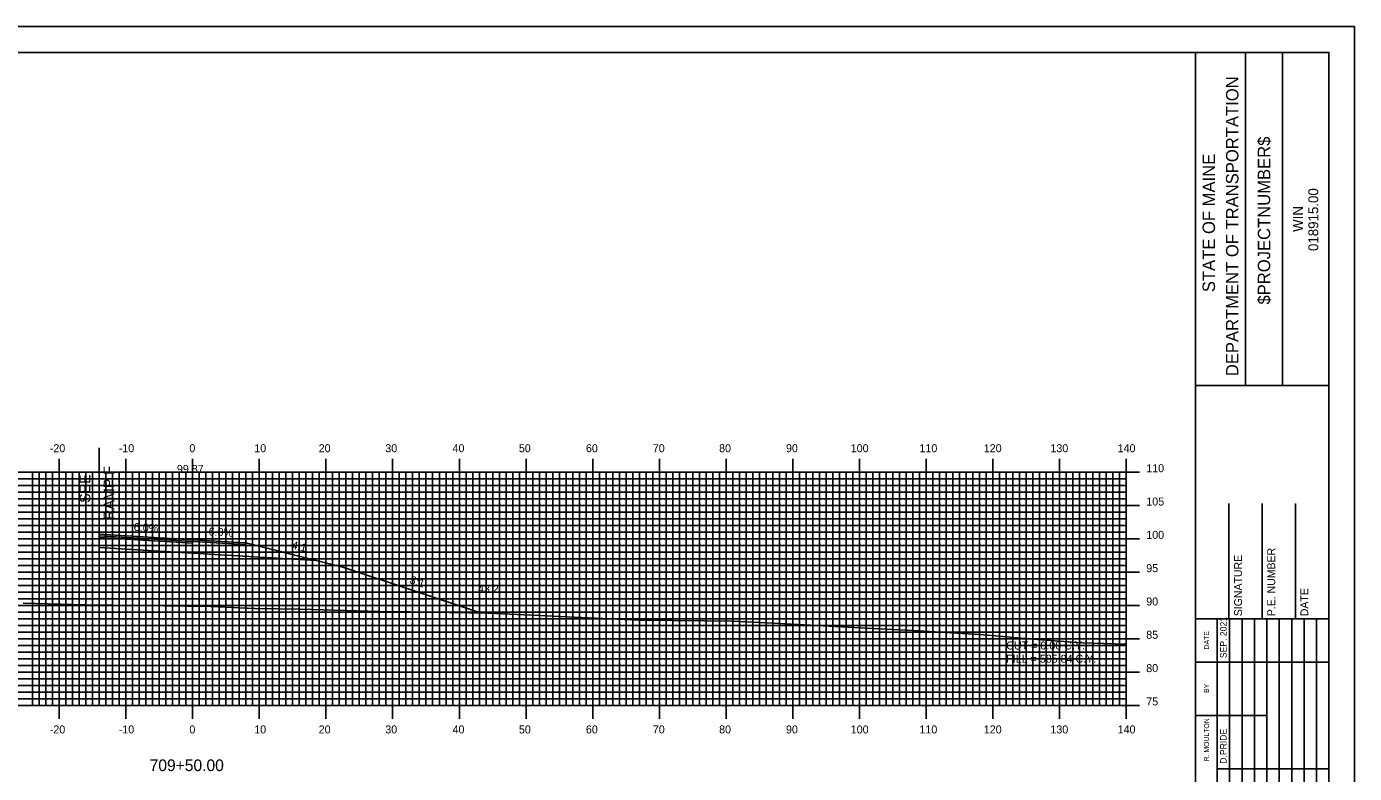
# Model space of a CAD drawing. Extents: x 854510 to 854853, y 364366 to 364586.
# Drawn here: x 854650.8 to 854850, y 364473.6 to 364585.7 of the extents above; entities that cross this region are included whole.
import ezdxf

# ---------------------------------------------------------------- set-up
doc = ezdxf.new("R2010")
doc.units = 0
for name, color, linetype in [('ANNOTATION', 7, 'Continuous'), ('BORDER', 7, 'Continuous'), ('D_Roadway_Centerline', 7, 'Continuous'), ('D_Roadway_Centerline_Text', 7, 'Continuous'), ('D_Roadway_Edge_Shoulder', 7, 'Continuous'), ('D_Roadway_Edge_TW', 7, 'Continuous'), ('D_Roadway_Pavement', 7, 'Continuous'), ('D_Roadway_SlopeLines', 7, 'Continuous'), ('D_Roadway_SubGrade', 7, 'Continuous'), ('D_Text_Standard', 7, 'Continuous'), ('H_V ANNOTATION', 7, 'Continuous'), ('MAJOR', 7, 'Continuous'), ('MINOR', 7, 'Continuous'), ('PLOT BOUNDARY', 7, 'Continuous'), ('S_Roadway_Centerline', 7, 'Continuous')]:
    doc.layers.add(name, color=color, linetype=linetype)

msp = doc.modelspace()

# ---------------------------------------------------------------- linework, layer by layer
at = {"layer": 'BORDER'}
for p, q in [((854826.14, 364371.79), (854826.14, 364581.79)), ((854833.6, 364531.78), (854833.6, 364581.78)), ((854839.19, 364531.78), (854839.19, 364581.78)), ((854826.15, 364531.78), (854846.14, 364531.78)), ((854831.14, 364496.79), (854831.14, 364514.09)), ((854836.14, 364496.79), (854836.14, 364514.09)), ((854841.14, 364496.79), (854841.14, 364514.09)), ((854826.14, 364496.79), (854846.14, 364496.79))]:
    msp.add_line(p, q, dxfattribs=at)
msp.add_lwpolyline([(854526.14, 364371.79), (854846.14, 364371.79), (854846.14, 364581.79), (854526.14, 364581.79)], close=True, dxfattribs=at)
for points in [[(854829.37, 364490.29), (854829.37, 364496.79)], [(854831.24, 364461.8), (854831.24, 364496.79)], [(854833.1, 364496.79), (854833.1, 364461.8)], [(854834.97, 364461.8), (854834.97, 364496.79)], [(854836.83, 364461.8), (854836.83, 364496.79)], [(854838.69, 364461.8), (854838.69, 364496.79)], [(854840.56, 364461.8), (854840.56, 364496.79)], [(854842.42, 364461.8), (854842.42, 364496.79)], [(854844.28, 364461.8), (854844.28, 364496.79)], [(854829.38, 364461.8), (854829.38, 364495.38)], [(854826.14, 364490.29), (854846.14, 364490.29)], [(854826.14, 364482.29), (854829.38, 364482.29)], [(854829.37, 364482.29), (854836.83, 364482.29)], [(854829.37, 364474.29), (854846.14, 364474.29)]]:
    msp.add_lwpolyline(points, dxfattribs=at)
at = {"layer": 'D_Roadway_Centerline'}
msp.add_lwpolyline([(854661.74, 364509.5), (854675.74, 364508.66), (854683.74, 364508.18), (854694.27, 364505.55), (854698.27, 364504.55), (854718.91, 364497.67)], dxfattribs=at)
at = {"layer": 'D_Roadway_Edge_Shoulder'}
msp.add_lwpolyline([(854675.74, 364508.66), (854683.74, 364508.18), (854683.74, 364507.93), (854675.74, 364508.41)], close=True, dxfattribs=at)
at = {"layer": 'D_Roadway_Edge_TW'}
msp.add_lwpolyline([(854661.74, 364509.5), (854675.74, 364508.66), (854675.74, 364508.41), (854661.74, 364509.25)], close=True, dxfattribs=at)
at = {"layer": 'D_Roadway_Pavement'}
msp.add_lwpolyline([(854661.74, 364509.25), (854675.74, 364508.41), (854675.74, 364508.16), (854661.74, 364509)], close=True, dxfattribs=at)
msp.add_lwpolyline([(854675.74, 364508.41), (854675.74, 364508.16)], dxfattribs=at)
at = {"layer": 'D_Roadway_SlopeLines'}
msp.add_lwpolyline([(854683.74, 364508.18), (854698.27, 364504.55), (854718.91, 364497.67)], dxfattribs=at)
at = {"layer": 'D_Roadway_SubGrade'}
msp.add_line((854661.74, 364522.46), (854661.74, 364507.5), dxfattribs=at)
for points in [[(854661.74, 364509), (854675.74, 364508.16), (854675.74, 364506.66), (854661.74, 364507.5)], [(854675.74, 364508.16), (854675.74, 364508.41), (854683.74, 364507.93), (854683.74, 364508.18), (854694.27, 364505.55), (854675.74, 364506.66)]]:
    msp.add_lwpolyline(points, close=True, dxfattribs=at)
at = {"layer": 'MAJOR'}
for p, q in [((854655.74, 364520.79), (854655.74, 364518.79)), ((854665.74, 364520.79), (854665.74, 364518.79)), ((854675.74, 364520.79), (854675.74, 364518.79)), ((854685.74, 364520.79), (854685.74, 364518.79)), ((854695.74, 364520.79), (854695.74, 364518.79)), ((854705.74, 364520.79), (854705.74, 364518.79)), ((854715.74, 364520.79), (854715.74, 364518.79)), ((854725.74, 364520.79), (854725.74, 364518.79)), ((854735.74, 364520.79), (854735.74, 364518.79)), ((854745.74, 364520.79), (854745.74, 364518.79)), ((854755.74, 364520.79), (854755.74, 364518.79)), ((854765.74, 364520.79), (854765.74, 364518.79)), ((854775.74, 364520.79), (854775.74, 364518.79)), ((854785.74, 364520.79), (854785.74, 364518.79)), ((854795.74, 364520.79), (854795.74, 364518.79)), ((854805.74, 364520.79), (854805.74, 364518.79)), ((854815.74, 364520.79), (854815.74, 364518.79)), ((854535.74, 364518.79), (854815.74, 364518.79)), ((854535.74, 364518.79), (854815.74, 364518.79)), ((854655.74, 364483.79), (854655.74, 364518.79)), ((854665.74, 364483.79), (854665.74, 364518.79)), ((854675.74, 364483.79), (854675.74, 364518.79)), ((854685.74, 364483.79), (854685.74, 364518.79)), ((854695.74, 364483.79), (854695.74, 364518.79)), ((854705.74, 364483.79), (854705.74, 364518.79)), ((854715.74, 364483.79), (854715.74, 364518.79)), ((854725.74, 364483.79), (854725.74, 364518.79)), ((854735.74, 364483.79), (854735.74, 364518.79)), ((854745.74, 364483.79), (854745.74, 364518.79)), ((854755.74, 364483.79), (854755.74, 364518.79)), ((854765.74, 364483.79), (854765.74, 364518.79)), ((854775.74, 364483.79), (854775.74, 364518.79)), ((854785.74, 364483.79), (854785.74, 364518.79)), ((854795.74, 364483.79), (854795.74, 364518.79)), ((854805.74, 364483.79), (854805.74, 364518.79)), ((854817.75, 364518.79), (854813.74, 364518.79)), ((854815.74, 364483.79), (854815.74, 364518.79)), ((854815.74, 364483.79), (854815.74, 364518.79)), ((854535.74, 364513.79), (854815.74, 364513.79)), ((854817.75, 364513.79), (854813.74, 364513.79)), ((854535.74, 364508.79), (854815.74, 364508.79)), ((854817.75, 364508.79), (854813.74, 364508.79)), ((854535.74, 364503.79), (854815.74, 364503.79)), ((854817.75, 364503.79), (854813.74, 364503.79)), ((854535.74, 364498.79), (854815.74, 364498.79)), ((854817.75, 364498.79), (854813.74, 364498.79)), ((854535.74, 364493.79), (854815.74, 364493.79)), ((854817.75, 364493.79), (854813.74, 364493.79)), ((854535.74, 364488.79), (854815.74, 364488.79)), ((854817.75, 364488.79), (854813.74, 364488.79)), ((854535.74, 364483.79), (854815.74, 364483.79)), ((854535.74, 364483.79), (854815.74, 364483.79)), ((854655.74, 364481.78), (854655.74, 364483.79)), ((854665.74, 364481.78), (854665.74, 364483.79)), ((854675.74, 364481.78), (854675.74, 364483.79)), ((854685.74, 364481.78), (854685.74, 364483.79)), ((854695.74, 364481.78), (854695.74, 364483.79)), ((854705.74, 364481.78), (854705.74, 364483.79)), ((854715.74, 364481.78), (854715.74, 364483.79)), ((854725.74, 364481.78), (854725.74, 364483.79)), ((854735.74, 364481.78), (854735.74, 364483.79)), ((854745.74, 364481.78), (854745.74, 364483.79)), ((854755.74, 364481.78), (854755.74, 364483.79)), ((854765.74, 364481.78), (854765.74, 364483.79)), ((854775.74, 364481.78), (854775.74, 364483.79)), ((854785.74, 364481.78), (854785.74, 364483.79)), ((854795.74, 364481.78), (854795.74, 364483.79)), ((854805.74, 364481.78), (854805.74, 364483.79)), ((854817.75, 364483.79), (854813.74, 364483.79)), ((854815.74, 364481.78), (854815.74, 364483.79))]:
    msp.add_line(p, q, dxfattribs=at)
at = {"layer": 'MINOR'}
for p, q in [((854535.74, 364517.79), (854815.74, 364517.79)), ((854651.74, 364483.79), (854651.74, 364518.79)), ((854652.74, 364483.79), (854652.74, 364518.79)), ((854653.74, 364483.79), (854653.74, 364518.79)), ((854654.74, 364483.79), (854654.74, 364518.79)), ((854656.74, 364483.79), (854656.74, 364518.79)), ((854657.74, 364483.79), (854657.74, 364518.79)), ((854658.74, 364483.79), (854658.74, 364518.79)), ((854659.74, 364483.79), (854659.74, 364518.79)), ((854660.74, 364483.79), (854660.74, 364518.79)), ((854661.74, 364483.79), (854661.74, 364518.79)), ((854662.74, 364483.79), (854662.74, 364518.79)), ((854663.74, 364483.79), (854663.74, 364518.79)), ((854664.74, 364483.79), (854664.74, 364518.79)), ((854666.74, 364483.79), (854666.74, 364518.79)), ((854667.74, 364483.79), (854667.74, 364518.79)), ((854668.74, 364483.79), (854668.74, 364518.79)), ((854669.74, 364483.79), (854669.74, 364518.79)), ((854670.74, 364483.79), (854670.74, 364518.79)), ((854671.74, 364483.79), (854671.74, 364518.79)), ((854672.74, 364483.79), (854672.74, 364518.79)), ((854673.74, 364483.79), (854673.74, 364518.79)), ((854674.74, 364483.79), (854674.74, 364518.79)), ((854676.74, 364483.79), (854676.74, 364518.79)), ((854677.74, 364483.79), (854677.74, 364518.79)), ((854678.74, 364483.79), (854678.74, 364518.79)), ((854679.74, 364483.79), (854679.74, 364518.79)), ((854680.74, 364483.79), (854680.74, 364518.79)), ((854681.74, 364483.79), (854681.74, 364518.79)), ((854682.74, 364483.79), (854682.74, 364518.79)), ((854683.74, 364483.79), (854683.74, 364518.79)), ((854684.74, 364483.79), (854684.74, 364518.79)), ((854686.74, 364483.79), (854686.74, 364518.79)), ((854687.74, 364483.79), (854687.74, 364518.79)), ((854688.74, 364483.79), (854688.74, 364518.79)), ((854689.74, 364483.79), (854689.74, 364518.79)), ((854690.74, 364483.79), (854690.74, 364518.79)), ((854691.74, 364483.79), (854691.74, 364518.79)), ((854692.74, 364483.79), (854692.74, 364518.79)), ((854693.74, 364483.79), (854693.74, 364518.79)), ((854694.74, 364483.79), (854694.74, 364518.79)), ((854696.74, 364483.79), (854696.74, 364518.79)), ((854697.74, 364483.79), (854697.74, 364518.79)), ((854698.74, 364483.79), (854698.74, 364518.79)), ((854699.74, 364483.79), (854699.74, 364518.79)), ((854700.74, 364483.79), (854700.74, 364518.79)), ((854701.74, 364483.79), (854701.74, 364518.79)), ((854702.74, 364483.79), (854702.74, 364518.79)), ((854703.74, 364483.79), (854703.74, 364518.79)), ((854704.74, 364483.79), (854704.74, 364518.79)), ((854706.74, 364483.79), (854706.74, 364518.79)), ((854707.74, 364483.79), (854707.74, 364518.79)), ((854708.74, 364483.79), (854708.74, 364518.79)), ((854709.74, 364483.79), (854709.74, 364518.79)), ((854710.74, 364483.79), (854710.74, 364518.79)), ((854711.74, 364483.79), (854711.74, 364518.79)), ((854712.74, 364483.79), (854712.74, 364518.79)), ((854713.74, 364483.79), (854713.74, 364518.79)), ((854714.74, 364483.79), (854714.74, 364518.79)), ((854716.74, 364483.79), (854716.74, 364518.79)), ((854717.74, 364483.79), (854717.74, 364518.79)), ((854718.74, 364483.79), (854718.74, 364518.79)), ((854719.74, 364483.79), (854719.74, 364518.79)), ((854720.74, 364483.79), (854720.74, 364518.79)), ((854721.74, 364483.79), (854721.74, 364518.79)), ((854722.74, 364483.79), (854722.74, 364518.79)), ((854723.74, 364483.79), (854723.74, 364518.79)), ((854724.74, 364483.79), (854724.74, 364518.79)), ((854726.74, 364483.79), (854726.74, 364518.79)), ((854727.74, 364483.79), (854727.74, 364518.79)), ((854728.74, 364483.79), (854728.74, 364518.79)), ((854729.74, 364483.79), (854729.74, 364518.79)), ((854730.74, 364483.79), (854730.74, 364518.79)), ((854731.74, 364483.79), (854731.74, 364518.79)), ((854732.74, 364483.79), (854732.74, 364518.79)), ((854733.74, 364483.79), (854733.74, 364518.79)), ((854734.74, 364483.79), (854734.74, 364518.79)), ((854736.74, 364483.79), (854736.74, 364518.79)), ((854737.74, 364483.79), (854737.74, 364518.79)), ((854738.74, 364483.79), (854738.74, 364518.79)), ((854739.74, 364483.79), (854739.74, 364518.79)), ((854740.74, 364483.79), (854740.74, 364518.79)), ((854741.74, 364483.79), (854741.74, 364518.79)), ((854742.74, 364483.79), (854742.74, 364518.79)), ((854743.74, 364483.79), (854743.74, 364518.79)), ((854744.74, 364483.79), (854744.74, 364518.79)), ((854746.74, 364483.79), (854746.74, 364518.79)), ((854747.74, 364483.79), (854747.74, 364518.79)), ((854748.74, 364483.79), (854748.74, 364518.79)), ((854749.74, 364483.79), (854749.74, 364518.79)), ((854750.74, 364483.79), (854750.74, 364518.79)), ((854751.74, 364483.79), (854751.74, 364518.79)), ((854752.74, 364483.79), (854752.74, 364518.79)), ((854753.74, 364483.79), (854753.74, 364518.79)), ((854754.74, 364483.79), (854754.74, 364518.79)), ((854756.74, 364483.79), (854756.74, 364518.79)), ((854757.74, 364483.79), (854757.74, 364518.79)), ((854758.74, 364483.79), (854758.74, 364518.79)), ((854759.74, 364483.79), (854759.74, 364518.79)), ((854760.74, 364483.79), (854760.74, 364518.79)), ((854761.74, 364483.79), (854761.74, 364518.79)), ((854762.74, 364483.79), (854762.74, 364518.79)), ((854763.74, 364483.79), (854763.74, 364518.79)), ((854764.74, 364483.79), (854764.74, 364518.79)), ((854766.74, 364483.79), (854766.74, 364518.79)), ((854767.74, 364483.79), (854767.74, 364518.79)), ((854768.74, 364483.79), (854768.74, 364518.79)), ((854769.74, 364483.79), (854769.74, 364518.79)), ((854770.74, 364483.79), (854770.74, 364518.79)), ((854771.74, 364483.79), (854771.74, 364518.79)), ((854772.74, 364483.79), (854772.74, 364518.79)), ((854773.74, 364483.79), (854773.74, 364518.79)), ((854774.74, 364483.79), (854774.74, 364518.79)), ((854776.74, 364483.79), (854776.74, 364518.79)), ((854777.74, 364483.79), (854777.74, 364518.79)), ((854778.74, 364483.79), (854778.74, 364518.79)), ((854779.74, 364483.79), (854779.74, 364518.79)), ((854780.74, 364483.79), (854780.74, 364518.79)), ((854781.74, 364483.79), (854781.74, 364518.79)), ((854782.74, 364483.79), (854782.74, 364518.79)), ((854783.74, 364483.79), (854783.74, 364518.79)), ((854784.74, 364483.79), (854784.74, 364518.79)), ((854786.74, 364483.79), (854786.74, 364518.79)), ((854787.74, 364483.79), (854787.74, 364518.79)), ((854788.74, 364483.79), (854788.74, 364518.79)), ((854789.74, 364483.79), (854789.74, 364518.79)), ((854790.74, 364483.79), (854790.74, 364518.79)), ((854791.74, 364483.79), (854791.74, 364518.79)), ((854792.74, 364483.79), (854792.74, 364518.79)), ((854793.74, 364483.79), (854793.74, 364518.79)), ((854794.74, 364483.79), (854794.74, 364518.79)), ((854796.74, 364483.79), (854796.74, 364518.79)), ((854797.74, 364483.79), (854797.74, 364518.79)), ((854798.74, 364483.79), (854798.74, 364518.79)), ((854799.74, 364483.79), (854799.74, 364518.79)), ((854800.74, 364483.79), (854800.74, 364518.79)), ((854801.74, 364483.79), (854801.74, 364518.79)), ((854802.74, 364483.79), (854802.74, 364518.79)), ((854803.74, 364483.79), (854803.74, 364518.79)), ((854804.74, 364483.79), (854804.74, 364518.79)), ((854806.74, 364483.79), (854806.74, 364518.79)), ((854807.74, 364483.79), (854807.74, 364518.79)), ((854808.74, 364483.79), (854808.74, 364518.79)), ((854809.74, 364483.79), (854809.74, 364518.79)), ((854810.74, 364483.79), (854810.74, 364518.79)), ((854811.74, 364483.79), (854811.74, 364518.79)), ((854812.74, 364483.79), (854812.74, 364518.79)), ((854813.74, 364483.79), (854813.74, 364518.79)), ((854815.74, 364517.79), (854813.74, 364517.79)), ((854814.74, 364483.79), (854814.74, 364518.79)), ((854535.74, 364516.79), (854815.74, 364516.79)), ((854535.74, 364515.79), (854815.74, 364515.79)), ((854815.74, 364516.79), (854813.74, 364516.79)), ((854815.74, 364515.79), (854813.74, 364515.79)), ((854535.74, 364514.79), (854815.74, 364514.79)), ((854815.74, 364514.79), (854813.74, 364514.79)), ((854535.74, 364512.79), (854815.74, 364512.79)), ((854535.74, 364511.79), (854815.74, 364511.79)), ((854815.74, 364512.79), (854813.74, 364512.79)), ((854815.74, 364511.79), (854813.74, 364511.79)), ((854535.74, 364510.79), (854815.74, 364510.79)), ((854535.74, 364509.79), (854815.74, 364509.79)), ((854815.74, 364510.79), (854813.74, 364510.79)), ((854815.74, 364509.79), (854813.74, 364509.79)), ((854535.74, 364507.79), (854815.74, 364507.79)), ((854815.74, 364507.79), (854813.74, 364507.79)), ((854535.74, 364506.79), (854815.74, 364506.79)), ((854535.74, 364505.79), (854815.74, 364505.79)), ((854815.74, 364506.79), (854813.74, 364506.79)), ((854815.74, 364505.79), (854813.74, 364505.79)), ((854535.74, 364504.79), (854815.74, 364504.79)), ((854815.74, 364504.79), (854813.74, 364504.79)), ((854535.74, 364502.79), (854815.74, 364502.79)), ((854535.74, 364501.79), (854815.74, 364501.79)), ((854815.74, 364502.79), (854813.74, 364502.79)), ((854815.74, 364501.79), (854813.74, 364501.79)), ((854535.74, 364500.79), (854815.74, 364500.79)), ((854535.74, 364499.79), (854815.74, 364499.79)), ((854815.74, 364500.79), (854813.74, 364500.79)), ((854815.74, 364499.79), (854813.74, 364499.79)), ((854535.74, 364497.79), (854815.74, 364497.79)), ((854815.74, 364497.79), (854813.74, 364497.79)), ((854535.74, 364496.79), (854815.74, 364496.79)), ((854535.74, 364495.79), (854815.74, 364495.79)), ((854815.74, 364496.79), (854813.74, 364496.79)), ((854815.74, 364495.79), (854813.74, 364495.79)), ((854535.74, 364494.79), (854815.74, 364494.79)), ((854815.74, 364494.79), (854813.74, 364494.79)), ((854535.74, 364492.79), (854815.74, 364492.79)), ((854815.74, 364492.79), (854813.74, 364492.79)), ((854535.74, 364491.79), (854815.74, 364491.79)), ((854535.74, 364490.79), (854815.74, 364490.79)), ((854815.74, 364491.79), (854813.74, 364491.79)), ((854815.74, 364490.79), (854813.74, 364490.79)), ((854535.74, 364489.79), (854815.74, 364489.79)), ((854815.74, 364489.79), (854813.74, 364489.79)), ((854535.74, 364487.79), (854815.74, 364487.79)), ((854535.74, 364486.79), (854815.74, 364486.79)), ((854815.74, 364487.79), (854813.74, 364487.79)), ((854815.74, 364486.79), (854813.74, 364486.79)), ((854535.74, 364485.79), (854815.74, 364485.79)), ((854535.74, 364484.79), (854815.74, 364484.79)), ((854815.74, 364485.79), (854813.74, 364485.79)), ((854815.74, 364484.79), (854813.74, 364484.79))]:
    msp.add_line(p, q, dxfattribs=at)
at = {"layer": 'PLOT BOUNDARY'}
msp.add_lwpolyline([(854509.96, 364365.67), (854849.96, 364365.67), (854849.96, 364585.67), (854509.96, 364585.67)], close=True, dxfattribs=at)
at = {"layer": 'S_Roadway_Centerline'}
msp.add_lwpolyline([(854650.32, 364499.13), (854659.66, 364498.9), (854667.94, 364498.79), (854678.5, 364498.62), (854685.03, 364498.32), (854691.86, 364498.26), (854703.71, 364497.88), (854708.37, 364497.82), (854720.06, 364497.65), (854729.8, 364497.19), (854738.31, 364496.77), (854742.68, 364496.59), (854752.44, 364496.5), (854756.9, 364496.43), (854768.38, 364495.84), (854773.11, 364495.59), (854784.64, 364494.98), (854791.12, 364494.58), (854793.86, 364494.44), (854801.1, 364493.81), (854809.05, 364493.16), (854815.74, 364492.98)], dxfattribs=at)

# ---------------------------------------------------------------- texts
at = {"layer": 'ANNOTATION'}
for s, height, rotation, p in [('SEE', 1.6, 90, (854660.4, 364514.18)), ('RAMP F', 1.6, 90, (854664, 364511.64)), ('6.0%', 1.2, 356.5664, (854666.9, 364509.99)), ('-6.0%', 1.2, 356.5664, (854677.58, 364509.35)), ('4:1', 1.2, 345.9638, (854690.51, 364507.35)), ('3:1', 1.2, 341.5652, (854708.19, 364502.15))]:
    msp.add_text(s, height=height, rotation=rotation, dxfattribs=at).set_placement(p)
at = {"layer": 'BORDER'}
for s, height, p in [('DEPARTMENT OF TRANSPORTATION', 1.8635, (854832.56, 364533.2)), ('$PROJECTNUMBER$', 1.8635, (854837.33, 364543.95)), ('STATE OF MAINE', 1.8635, (854829.05, 364545.81)), ('018915.00', 1.491, (854844.53, 364551.98)), ('WIN', 1.491, (854842.22, 364554.85)), ('SIGNATURE', 1.181, (854833.1, 364497.18)), ('P.E. NUMBER', 1.1811, (854838.07, 364497.18)), ('DATE', 1.181, (854843.03, 364497.18)), ('SEP. 2021', 0.969, (854830.79, 364490.88)), ('DATE', 0.743, (854828.15, 364492.2)), ('BY', 0.743, (854828.15, 364485.66)), ('R. MOULTON', 0.745, (854828.15, 364475.4)), ('D.PRIDE', 0.969, (854830.79, 364475.04))]:
    msp.add_text(s, height=height, rotation=90, dxfattribs=at).set_placement(p)
at = {"layer": 'D_Roadway_Centerline_Text'}
msp.add_text('99.87', height=1.2, dxfattribs=at).set_placement((854673.39, 364518.68))
at = {"layer": 'D_Text_Standard'}
for s, p in [("43.2'", (854718.53, 364500.69)), ('CUT = 0.00 C.Y.', (854797.74, 364492.19)), ('FILL = 585.84 C.Y.', (854797.74, 364490.2))]:
    msp.add_text(s, height=1.2, dxfattribs=at).set_placement(p)
at = {"layer": 'H_V ANNOTATION'}
for s, height, p in [('-20', 1.2, (854654.33, 364521.79)), ('-10', 1.2, (854664.67, 364521.79)), ('0', 1.2, (854675.26, 364521.79)), ('10', 1.2, (854684.99, 364521.79)), ('20', 1.2, (854694.65, 364521.79)), ('30', 1.2, (854704.64, 364521.79)), ('40', 1.2, (854714.72, 364521.79)), ('50', 1.2, (854724.67, 364521.79)), ('60', 1.2, (854734.72, 364521.79)), ('70', 1.2, (854744.75, 364521.79)), ('80', 1.2, (854754.69, 364521.79)), ('90', 1.2, (854764.72, 364521.79)), ('100', 1.2, (854774.43, 364521.79)), ('110', 1.2, (854784.73, 364521.79)), ('120', 1.2, (854794.38, 364521.79)), ('130', 1.2, (854804.37, 364521.79)), ('140', 1.2, (854814.45, 364521.79)), ('110', 1.2, (854818.74, 364518.79)), ('105', 1.2, (854818.74, 364513.79)), ('100', 1.2, (854818.74, 364508.79)), ('95', 1.2, (854818.74, 364503.79)), ('90', 1.2, (854818.74, 364498.79)), ('85', 1.2, (854818.74, 364493.79)), ('80', 1.2, (854818.74, 364488.79)), ('75', 1.2, (854818.74, 364483.79)), ('-20', 1.2, (854654.33, 364479.59)), ('-10', 1.2, (854664.67, 364479.59)), ('0', 1.2, (854675.26, 364479.59)), ('10', 1.2, (854684.99, 364479.59)), ('20', 1.2, (854694.65, 364479.59)), ('30', 1.2, (854704.64, 364479.59)), ('40', 1.2, (854714.72, 364479.59)), ('50', 1.2, (854724.67, 364479.59)), ('60', 1.2, (854734.72, 364479.59)), ('70', 1.2, (854744.75, 364479.59)), ('80', 1.2, (854754.69, 364479.59)), ('90', 1.2, (854764.72, 364479.59)), ('100', 1.2, (854774.43, 364479.59)), ('110', 1.2, (854784.73, 364479.59)), ('120', 1.2, (854794.38, 364479.59)), ('130', 1.2, (854804.37, 364479.59)), ('140', 1.2, (854814.45, 364479.59)), ('709+50.00', 1.75, (854669.3, 364473.94))]:
    msp.add_text(s, height=height, dxfattribs=at).set_placement(p)

doc.saveas('drawing.dxf')
